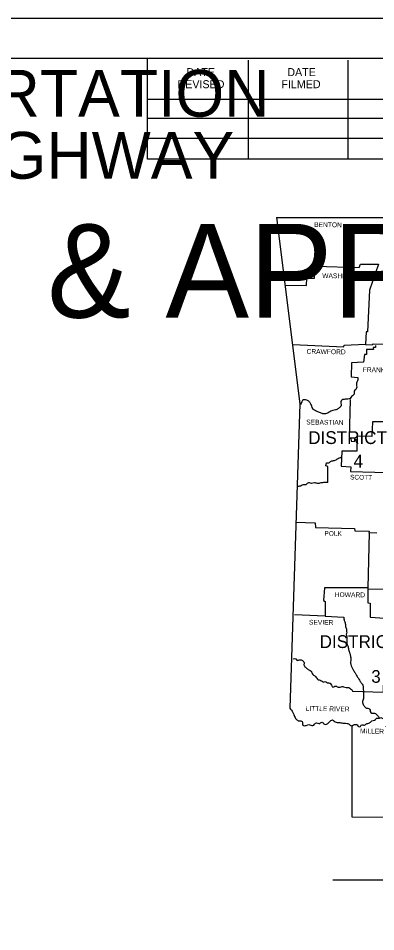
# Model space of a CAD drawing. Extents: x 1369885 to 1370219, y 379980 to 380218.
# Drawn here: x 1370119.1 to 1370154, y 380128.7 to 380217.9 of the extents above; entities that cross this region are included whole.
import ezdxf

# ---------------------------------------------------------------- set-up
doc = ezdxf.new("R2010")
doc.units = 0
for name, color, linetype in [('Default', 7, 'Continuous'), ('Level 2', 7, 'Continuous'), ('R_No Plot', 7, 'Continuous'), ('STAMP_PE_FOSTER-SIGNATURE', 7, 'Continuous')]:
    doc.layers.add(name, color=color, linetype=linetype)

msp = doc.modelspace()

# ---------------------------------------------------------------- linework, layer by layer
at = {"layer": 'Default'}
msp.add_line((1370149.848, 380133.736), (1370199.392, 380133.736), dxfattribs=at)
for points in [[(1370144.335, 380198.452), (1370162.058, 380198.442), (1370177.609, 380198.482), (1370195.96, 380198.761), (1370204.458, 380198.96)], [(1370144.335, 380198.452), (1370146.606, 380180.24), (1370145.62, 380150.512)], [(1370145.161, 380191.827), (1370147.254, 380191.817), (1370147.313, 380192.534), (1370148.061, 380192.534), (1370148.13, 380193.71), (1370152.404, 380193.56), (1370152.534, 380193.889), (1370154.297, 380193.899), (1370153.41, 380191.358), (1370153.241, 380187.294), (1370153.102, 380187.274), (1370153.042, 380186.048), (1370153.689, 380185.999), (1370153.789, 380186.098), (1370159.009, 380185.999), (1370159.069, 380185.411)], [(1370145.929, 380186.038), (1370150.91, 380185.809), (1370150.94, 380185.989), (1370153.022, 380186.078)], [(1370154.008, 380185.949), (1370154.008, 380185.76), (1370153.799, 380185.76), (1370153.809, 380185.56), (1370153.141, 380185.55), (1370153.131, 380185.052), (1370152.942, 380185.052), (1370152.842, 380184.315), (1370151.657, 380184.265), (1370151.647, 380182.87), (1370152.285, 380182.831)], [(1370151.537, 380180.659), (1370151.428, 380176.893), (1370151.597, 380176.843), (1370151.627, 380176.584), (1370151.956, 380176.564), (1370151.986, 380176.744), (1370152.255, 380176.793)], [(1370155.224, 380180.071), (1370155.144, 380178.497), (1370153.719, 380178.487), (1370153.639, 380177.062), (1370152.225, 380177.092), (1370152.185, 380175.628), (1370150.711, 380175.618), (1370150.661, 380174.153), (1370151.597, 380174.094), (1370151.557, 380173.645), (1370156.319, 380173.516)], [(1370149.336, 380172.559), (1370149.366, 380174.103), (1370149.146, 380174.173), (1370149.216, 380174.462)], [(1370146.227, 380168.684), (1370148.12, 380168.614), (1370148.16, 380168.156), (1370151.956, 380168.076), (1370151.996, 380167.837), (1370153.38, 380167.797), (1370153.37, 380167.588)], [(1370154.128, 380167.588), (1370153.38, 380167.648), (1370153.261, 380162.258), (1370149.037, 380162.268), (1370148.937, 380161.023), (1370149.097, 380160.913), (1370149.087, 380159.509), (1370146.088, 380159.638)], [(1370153.261, 380162.258), (1370153.261, 380160.804), (1370153.5, 380160.754), (1370153.48, 380159.399), (1370154.925, 380159.289), (1370154.755, 380152.047), (1370151.767, 380152.126)], [(1370153.281, 380162.178), (1370159.547, 380162.019)], [(1370149.087, 380159.509), (1370150.9, 380159.399)], [(1370151.687, 380148.749), (1370151.707, 380139.883), (1370191.865, 380139.813)]]:
    msp.add_lwpolyline(points, dxfattribs=at)
for points in [[(1370152.285, 380182.831), (1370152.285, 380182.601), (1370152.195, 380182.352), (1370152.145, 380182.153), (1370152.175, 380181.874), (1370152.075, 380181.655), (1370151.936, 380181.476), (1370151.936, 380181.257), (1370151.767, 380181.027), (1370151.597, 380180.858), (1370151.438, 380180.719), (1370151.169, 380180.689), (1370150.94, 380180.679), (1370150.711, 380180.599), (1370150.621, 380180.44), (1370150.661, 380180.191), (1370150.571, 380179.941), (1370150.342, 380179.762), (1370150.093, 380179.643), (1370149.834, 380179.593), (1370149.465, 380179.423), (1370149.136, 380179.274), (1370148.788, 380179.304), (1370148.459, 380179.443), (1370148.16, 380179.573), (1370147.931, 380179.702), (1370147.752, 380180.111), (1370147.622, 380180.33), (1370147.423, 380180.549), (1370147.164, 380180.639), (1370146.955, 380180.619), (1370146.706, 380180.191)], [(1370149.216, 380174.462), (1370149.455, 380174.492), (1370149.684, 380174.641), (1370149.993, 380174.711), (1370150.302, 380174.871), (1370150.681, 380175.05)], [(1370149.336, 380172.559), (1370149.017, 380172.549), (1370148.658, 380172.509), (1370148.33, 380172.46), (1370148.031, 380172.519), (1370147.762, 380172.47), (1370147.572, 380172.519), (1370147.343, 380172.46), (1370147.214, 380172.33), (1370146.935, 380172.33), (1370146.736, 380172.241), (1370146.427, 380172.171)], [(1370150.9, 380159.399), (1370150.96, 380159.07), (1370151.059, 380158.781), (1370151.069, 380158.562), (1370151.169, 380158.233), (1370151.169, 380158.114), (1370151.199, 380157.875), (1370151.159, 380157.745), (1370151.209, 380157.476), (1370151.199, 380157.287), (1370151.199, 380157.118), (1370151.209, 380156.849), (1370151.298, 380156.599), (1370151.388, 380156.241), (1370151.438, 380156.052), (1370151.527, 380155.773), (1370151.587, 380155.424), (1370151.597, 380155.155), (1370151.567, 380154.916), (1370151.637, 380154.647), (1370151.757, 380154.368), (1370151.916, 380154.109), (1370152.095, 380153.81), (1370152.225, 380153.581), (1370152.394, 380153.332), (1370152.524, 380153.123), (1370152.723, 380152.854), (1370152.813, 380152.634), (1370152.813, 380152.326), (1370152.852, 380152.047), (1370152.842, 380151.728), (1370152.823, 380151.439), (1370152.743, 380151.05), (1370152.803, 380150.861), (1370153.012, 380150.592), (1370153.141, 380150.512), (1370153.37, 380150.463), (1370153.48, 380150.313), (1370153.54, 380150.084), (1370153.779, 380150.004), (1370154.028, 380149.984), (1370154.148, 380149.855), (1370154.317, 380149.676), (1370154.367, 380149.586)], [(1370145.958, 380155.314), (1370146.208, 380155.324), (1370146.367, 380155.175), (1370146.467, 380155.195), (1370146.646, 380155.215), (1370146.805, 380155.205), (1370146.925, 380155.105), (1370147.024, 380154.926), (1370147.014, 380154.766), (1370147.024, 380154.697), (1370147.104, 380154.557), (1370147.234, 380154.448), (1370147.373, 380154.338), (1370147.503, 380154.248), (1370147.722, 380154.109), (1370147.752, 380154.059), (1370147.831, 380153.89), (1370147.941, 380153.74), (1370148.08, 380153.661), (1370148.22, 380153.501), (1370148.28, 380153.441), (1370148.399, 380153.282), (1370148.519, 380153.272), (1370148.678, 380153.172), (1370148.798, 380153.143), (1370148.927, 380153.053), (1370149.067, 380153.093), (1370149.226, 380153.033), (1370149.445, 380152.963), (1370149.565, 380152.943), (1370149.714, 380152.734), (1370149.854, 380152.565), (1370150.023, 380152.654), (1370150.352, 380152.565), (1370150.561, 380152.545), (1370150.75, 380152.605), (1370150.89, 380152.595), (1370151.159, 380152.525), (1370151.318, 380152.525), (1370151.498, 380152.465), (1370151.657, 380152.326), (1370151.767, 380152.186), (1370151.767, 380152.126)], [(1370145.62, 380150.512), (1370145.939, 380150.094), (1370146.068, 380149.795), (1370146.257, 380149.417), (1370146.526, 380149.257), (1370146.845, 380149.207), (1370146.915, 380148.839), (1370147.244, 380148.819), (1370147.503, 380148.899), (1370147.871, 380148.799), (1370148.25, 380149.068), (1370148.469, 380148.998), (1370148.788, 380149.128), (1370149.027, 380148.928), (1370149.445, 380149.108), (1370149.814, 380149.347), (1370150.173, 380149.118), (1370150.511, 380149.088), (1370150.91, 380149.028), (1370151.229, 380149.008), (1370151.517, 380148.869), (1370151.727, 380148.729), (1370151.687, 380148.749)], [(1370151.687, 380148.749), (1370152.065, 380148.908), (1370152.225, 380148.859), (1370152.374, 380148.709), (1370152.534, 380148.709), (1370152.623, 380148.849), (1370152.793, 380148.859), (1370152.922, 380148.849), (1370153.062, 380148.928), (1370153.181, 380148.988), (1370153.351, 380149.038), (1370153.47, 380149.088), (1370153.58, 380149.207), (1370153.779, 380149.307), (1370154.008, 380149.387), (1370154.068, 380149.496), (1370154.177, 380149.536), (1370154.397, 380149.526), (1370154.546, 380149.586), (1370154.666, 380149.536), (1370154.775, 380149.456), (1370154.795, 380149.177), (1370154.885, 380149.018), (1370155.014, 380148.749), (1370155.204, 380148.6), (1370155.373, 380148.46), (1370155.443, 380148.371), (1370155.632, 380148.211), (1370155.791, 380148.151), (1370155.871, 380148.032), (1370155.991, 380147.753), (1370156.16, 380147.494)]]:
    msp.add_spline(points, degree=3, dxfattribs=at)
at = {"layer": 'R_No Plot'}
msp.add_line((1369885.407, 380217.922), (1370218.741, 380217.922), dxfattribs=at)
msp.add_lwpolyline([(1369885.401, 380217.922), (1370218.741, 380217.922), (1370218.741, 380004.585), (1369885.401, 380004.585)], close=True, dxfattribs=at)
at = {"layer": 'STAMP_PE_FOSTER-SIGNATURE'}
for p, q in [((1369897.808, 380214.028), (1370213.988, 380214.028)), ((1370131.728, 380204.148), (1370131.728, 380214.028)), ((1370141.588, 380204.148), (1370141.588, 380213.828)), ((1370151.348, 380204.148), (1370151.348, 380213.828)), ((1370131.728, 380210.008), (1370170.888, 380210.008)), ((1370131.728, 380208.148), (1370170.888, 380208.148)), ((1370131.728, 380204.148), (1370131.728, 380206.208)), ((1370131.728, 380206.208), (1370170.888, 380206.208)), ((1370213.988, 380204.148), (1370131.728, 380204.148))]:
    msp.add_line(p, q, dxfattribs=at)

# ---------------------------------------------------------------- texts
at = {"layer": 'Default'}
for s, height, rotation, p in [('BENTON', 0.4713, 359.25271, (1370148.011, 380197.525)), ('WASHINGTON', 0.4711, 359.23201, (1370148.798, 380192.534)), ('CRAWFORD', 0.4711, 359.27706, (1370147.264, 380185.132)), ('FRANKLIN', 0.4713, 359.18154, (1370152.763, 380183.349)), ('SEBASTIAN', 0.4711, 359.28159, (1370147.234, 380178.228)), ('SCOTT', 0.4603, 359.40628, (1370151.527, 380172.848)), ('POLK', 0.4601, 359.21517, (1370149.017, 380167.359)), ('HOWARD', 0.4713, 359.51446, (1370150.023, 380161.362)), ('SEVIER', 0.4713, 359.42706, (1370147.503, 380158.662)), ('LITTLE RIVER', 0.47126, 359.16968, (1370147.174, 380150.243)), ('MILLER', 0.4711, 359.13195, (1370152.494, 380148.042))]:
    msp.add_text(s, height=height, rotation=rotation, dxfattribs=at).set_placement(p)
for s, height, p in [('DISTRICT', 1.2493, (1370147.433, 380176.315)), ('4', 1.249, (1370151.866, 380174.014)), ('DISTRICT', 1.2493, (1370148.549, 380156.38)), ('3', 1.238, (1370153.6, 380152.983))]:
    msp.add_text(s, height=height, dxfattribs=at).set_placement(p)
at = {"layer": 'Level 2'}
for s, height, p in [('ARKANSAS DEPARTMENT OF TRANSPORTATION', 4.57836, (1369998.042, 380208.303)), ('CONSTRUCTION PLANS FOR STATE HIGHWAY', 4.57836, (1370002.1, 380202.242)), ('SPENCER CREEK STR. & APPRS. (S)', 9.16, (1369982.371, 380188.67))]:
    msp.add_text(s, height=height, dxfattribs=at).set_placement(p)
at = {"layer": 'STAMP_PE_FOSTER-SIGNATURE'}
for s, p in [('DATE', (1370135.528, 380212.268)), ('DATE', (1370145.388, 380212.268)), ('REVISED', (1370134.648, 380211.088)), ('FILMED', (1370144.808, 380211.088))]:
    msp.add_text(s, height=0.7819, dxfattribs=at).set_placement(p)

doc.saveas('drawing.dxf')
